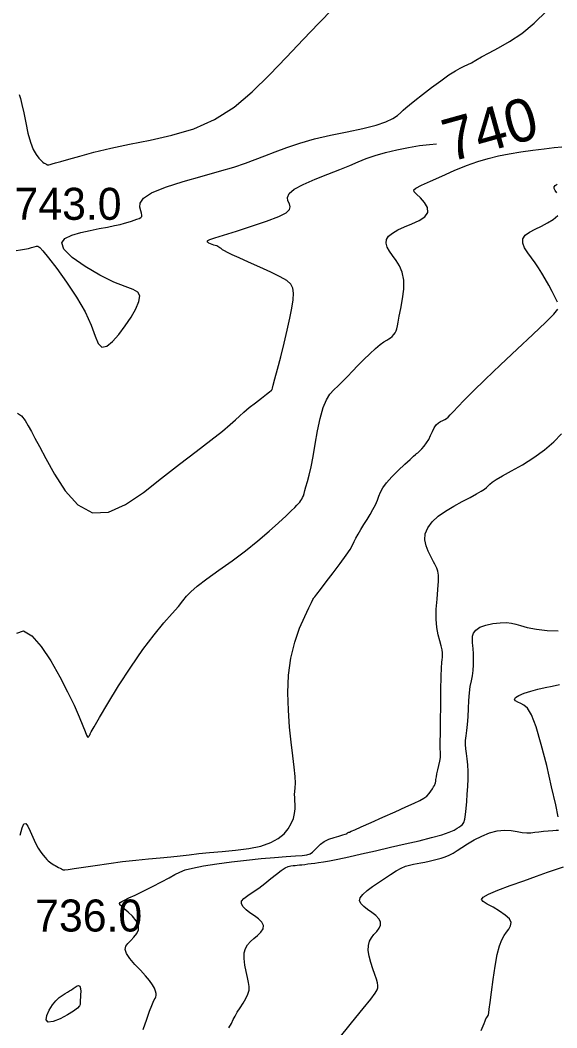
# Model space of a CAD drawing. Extents: x 2566142 to 2571431, y 418755 to 421584.
# Drawn here: x 2570246.2 to 2570497.9, y 419800.8 to 420273.2 of the extents above; entities that cross this region are included whole.
import ezdxf

# ---------------------------------------------------------------- set-up
doc = ezdxf.new("R2010")
doc.units = 0
for name, color, linetype in [('Contour_ADS_Label_Major', 7, 'Continuous'), ('Contour_ADS_Major', 7, 'Continuous'), ('Contour_ADS_Minor', 7, 'Continuous'), ('Contour_ADS_Spot_Elevation', 7, 'Continuous')]:
    doc.layers.add(name, color=color, linetype=linetype)

msp = doc.modelspace()

# ---------------------------------------------------------------- linework, layer by layer
at = {"layer": 'Contour_ADS_Major'}
for points in [[(2570364.23, 420099.94), (2570364.25, 420099.97), (2570364.3, 420100.08), (2570364.47, 420100.66), (2570364.89, 420102.17), (2570365.66, 420105.07), (2570366.87, 420109.65), (2570368.36, 420115.44), (2570369.95, 420121.76), (2570371.45, 420127.94), (2570372.68, 420133.45), (2570373.59, 420138.15), (2570374.15, 420142.06), (2570374.32, 420145.18), (2570374.03, 420147.54), (2570373.06, 420149.43), (2570371.16, 420151.13), (2570368.06, 420152.95), (2570363.66, 420155.12), (2570358.51, 420157.47), (2570353.33, 420159.77), (2570348.83, 420161.75), (2570345.54, 420163.25), (2570343.34, 420164.31), (2570341.94, 420165.06), (2570341.04, 420165.63), (2570340.38, 420166.11), (2570339.86, 420166.53), (2570339.39, 420166.88), (2570338.9, 420167.16), (2570338.33, 420167.38), (2570337.68, 420167.56), (2570336.97, 420167.76), (2570336.21, 420168.01), (2570335.43, 420168.35), (2570334.72, 420168.75), (2570334.19, 420169.17), (2570333.93, 420169.56), (2570334.12, 420169.93), (2570335.15, 420170.41), (2570337.48, 420171.19), (2570341.58, 420172.46), (2570347.63, 420174.33), (2570354.73, 420176.6), (2570361.72, 420178.96), (2570367.41, 420181.15), (2570370.93, 420182.95), (2570372.56, 420184.43), (2570372.86, 420185.76), (2570372.41, 420187.08), (2570371.78, 420188.51), (2570371.56, 420190.13), (2570372.32, 420191.94), (2570374.65, 420193.97), (2570378.89, 420196.24), (2570384.45, 420198.62), (2570390.48, 420200.98), (2570396.13, 420203.17), (2570400.78, 420205.09), (2570404.74, 420206.78), (2570408.51, 420208.3), (2570412.63, 420209.73), (2570417.46, 420211.11), (2570422.79, 420212.4), (2570428.24, 420213.52), (2570433.43, 420214.4), (2570438.11, 420214.99), (2570441.48, 420215.29)], [(2570244.99, 420088.96), (2570246.77, 420087.73), (2570248.44, 420085.56), (2570249.98, 420083), (2570251.45, 420080.39), (2570253.09, 420077.35), (2570255.24, 420073.33), (2570258.21, 420067.74), (2570262.24, 420060.42), (2570267.29, 420052.63), (2570273.28, 420046.03), (2570280.08, 420042.27), (2570287.59, 420042.53), (2570295.61, 420046.11), (2570303.96, 420051.82), (2570312.45, 420058.47), (2570320.83, 420065.03), (2570328.69, 420071.08), (2570335.56, 420076.36), (2570340.99, 420080.61), (2570344.7, 420083.67), (2570347.16, 420085.87), (2570349.05, 420087.65), (2570351.05, 420089.45), (2570353.62, 420091.58), (2570356.53, 420093.89), (2570359.35, 420096.07), (2570361.65, 420097.83), (2570363.12, 420098.95), (2570363.88, 420099.54), (2570364.16, 420099.78), (2570364.2, 420099.84), (2570364.21, 420099.87), (2570364.22, 420099.9), (2570364.23, 420099.94)], [(2570498.54, 419899.8), (2570497.32, 419905.45), (2570495.44, 419913.85), (2570493.11, 419923.8), (2570490.59, 419933.71), (2570488.15, 419942.01), (2570486, 419947.52), (2570484.13, 419950.63), (2570482.46, 419952.15), (2570480.92, 419952.88), (2570479.5, 419953.47), (2570478.42, 419954.12), (2570477.99, 419954.84), (2570478.48, 419955.68), (2570480.09, 419956.67), (2570482.59, 419957.72), (2570485.68, 419958.74), (2570489.01, 419959.65), (2570492.35, 419960.38), (2570495.67, 419961.05), (2570499.04, 419961.8)], [(2570430.59, 419877.53), (2570432.34, 419877.83), (2570434.15, 419878.17), (2570436.01, 419878.57), (2570437.92, 419879), (2570439.84, 419879.44), (2570441.76, 419879.89), (2570443.67, 419880.39), (2570445.55, 419880.99), (2570447.38, 419881.76), (2570449.2, 419882.75), (2570451.12, 419883.96), (2570453.31, 419885.4), (2570455.94, 419887.07), (2570459.1, 419888.92), (2570462.63, 419890.75), (2570466.33, 419892.29), (2570469.96, 419893.28), (2570473.35, 419893.57), (2570476.44, 419893.34), (2570479.22, 419892.87), (2570481.65, 419892.44), (2570483.75, 419892.27), (2570485.65, 419892.32), (2570487.51, 419892.52), (2570489.48, 419892.77), (2570491.66, 419893), (2570493.88, 419893.19), (2570495.93, 419893.35), (2570497.57, 419893.47), (2570498.64, 419893.57)], [(2570395.13, 419795.21), (2570401.61, 419803.19), (2570407.02, 419809.86), (2570410.64, 419814.37), (2570412.69, 419817.07), (2570413.64, 419818.6), (2570413.92, 419819.62), (2570413.92, 419820.7), (2570413.69, 419822.02), (2570413.23, 419823.69), (2570412.53, 419825.83), (2570411.6, 419828.48), (2570410.62, 419831.44), (2570409.81, 419834.43), (2570409.37, 419837.18), (2570409.46, 419839.49), (2570410.03, 419841.41), (2570410.95, 419843.07), (2570412.11, 419844.58), (2570413.37, 419846.06), (2570414.49, 419847.52), (2570415.19, 419848.99), (2570415.22, 419850.47), (2570414.4, 419851.98), (2570412.92, 419853.49), (2570411.06, 419854.96), (2570409.13, 419856.36), (2570407.38, 419857.69), (2570406.06, 419858.99), (2570405.39, 419860.33), (2570405.6, 419861.79), (2570406.81, 419863.41), (2570408.85, 419865.17), (2570411.42, 419867.04), (2570414.26, 419868.98), (2570417.11, 419870.93), (2570419.87, 419872.79), (2570422.47, 419874.42), (2570424.84, 419875.72), (2570426.94, 419876.61), (2570428.82, 419877.16), (2570430.59, 419877.53)]]:
    msp.add_lwpolyline(points, dxfattribs=at)
at = {"layer": 'Contour_ADS_Minor'}
for points in [[(2570245.76, 420238.35), (2570246.34, 420236.47), (2570247.02, 420233.67), (2570247.83, 420229.71), (2570248.75, 420225.04), (2570249.8, 420220.27), (2570250.98, 420215.98), (2570252.28, 420212.66), (2570253.61, 420210.26), (2570254.87, 420208.58), (2570255.96, 420207.46), (2570256.8, 420206.71), (2570257.42, 420206.24), (2570257.87, 420205.97), (2570258.17, 420205.81), (2570258.39, 420205.68), (2570258.55, 420205.58), (2570258.68, 420205.5), (2570258.8, 420205.44), (2570258.94, 420205.4), (2570259.18, 420205.41), (2570259.57, 420205.47), (2570260.18, 420205.61), (2570261.13, 420205.85), (2570262.69, 420206.28), (2570265.18, 420206.98), (2570268.93, 420208.04), (2570274.16, 420209.51), (2570280.78, 420211.27), (2570288.62, 420213.2), (2570297.5, 420215.13), (2570307.21, 420217.03), (2570317.37, 420219.27), (2570327.57, 420222.3), (2570337.38, 420226.6), (2570346.49, 420232.48), (2570355, 420239.64), (2570363.11, 420247.6), (2570371.02, 420255.91), (2570378.82, 420264.11), (2570386.21, 420271.8), (2570392.78, 420278.55)], [(2570425.83, 420230.97), (2570427.09, 420232.07), (2570428.79, 420233.5), (2570431.32, 420235.53), (2570434.88, 420238.34), (2570439.09, 420241.59), (2570443.4, 420244.82), (2570447.27, 420247.56), (2570450.29, 420249.47), (2570452.58, 420250.72), (2570454.43, 420251.59), (2570456.1, 420252.37), (2570457.85, 420253.29), (2570459.95, 420254.48), (2570462.61, 420255.98), (2570466.07, 420257.87), (2570470.5, 420260.22), (2570475.69, 420263.2), (2570481.38, 420267), (2570487.3, 420271.81), (2570493.15, 420277.65)], [(2570244.31, 420165.29), (2570246.31, 420165.54), (2570248.25, 420165.85), (2570250, 420166.22), (2570251.52, 420166.6), (2570252.78, 420166.94), (2570253.76, 420167.2), (2570254.5, 420167.25), (2570255.38, 420166.68), (2570256.87, 420165.02), (2570259.42, 420161.81), (2570263.29, 420156.76), (2570267.95, 420150.37), (2570272.64, 420143.36), (2570276.64, 420136.42), (2570279.4, 420130.21), (2570281.27, 420125.14), (2570282.77, 420121.59), (2570284.46, 420119.93), (2570286.74, 420120.38), (2570289.5, 420122.55), (2570292.49, 420125.9), (2570295.47, 420129.89), (2570298.2, 420134.02), (2570300.41, 420137.96), (2570301.84, 420141.41), (2570302.23, 420144.05), (2570301.35, 420145.75), (2570299.09, 420146.97), (2570295.38, 420148.32), (2570290.16, 420150.44), (2570283.58, 420153.72), (2570276.63, 420157.78), (2570270.56, 420162.02), (2570266.6, 420165.84), (2570265.63, 420168.78), (2570267.19, 420170.91), (2570270.45, 420172.46), (2570274.62, 420173.64), (2570278.97, 420174.63), (2570283.19, 420175.48), (2570287.08, 420176.23), (2570290.43, 420176.89), (2570293.09, 420177.49), (2570295.17, 420178.04), (2570296.86, 420178.55), (2570298.32, 420179.01), (2570299.7, 420179.46), (2570300.95, 420179.89), (2570302, 420180.32), (2570302.77, 420180.75), (2570303.19, 420181.23), (2570303.3, 420181.83), (2570303.14, 420182.68), (2570302.74, 420183.87), (2570302.28, 420185.5), (2570302.43, 420187.5), (2570304.01, 420189.79), (2570307.81, 420192.3), (2570314.31, 420194.93), (2570322.61, 420197.56), (2570331.49, 420200.09), (2570339.73, 420202.38), (2570346.4, 420204.37), (2570351.78, 420206.14), (2570356.44, 420207.84), (2570360.96, 420209.61), (2570365.84, 420211.54), (2570371.27, 420213.57), (2570377.34, 420215.6), (2570384.18, 420217.53), (2570391.76, 420219.28), (2570399.54, 420220.9), (2570406.88, 420222.44), (2570413.1, 420223.98), (2570417.73, 420225.57), (2570420.95, 420227.14), (2570423.13, 420228.6), (2570424.63, 420229.89), (2570425.83, 420230.97)], [(2570426.42, 420176.29), (2570429.89, 420177.76), (2570433.25, 420179.33), (2570435.93, 420181.09), (2570437.36, 420183.09), (2570437.16, 420185.37), (2570435.78, 420187.72), (2570433.86, 420189.89), (2570432.04, 420191.63), (2570430.89, 420192.79), (2570430.73, 420193.64), (2570431.81, 420194.52), (2570434.4, 420195.81), (2570438.59, 420197.76), (2570443.92, 420200.16), (2570449.79, 420202.68), (2570455.57, 420205.02), (2570460.81, 420206.91), (2570465.67, 420208.4), (2570470.47, 420209.58), (2570475.51, 420210.58), (2570480.99, 420211.46), (2570486.61, 420212.24), (2570491.93, 420212.91), (2570496.55, 420213.46), (2570500.14, 420213.9)], [(2570497.9, 420192.28), (2570497.15, 420193.36), (2570496.68, 420194.25), (2570496.62, 420195.02), (2570497.08, 420195.71), (2570498.05, 420196.37)], [(2570498.13, 420141.01), (2570497.07, 420143.25), (2570495.69, 420146), (2570494.12, 420148.98), (2570492.47, 420151.93), (2570490.86, 420154.62), (2570489.25, 420157.11), (2570487.63, 420159.48), (2570485.95, 420161.82), (2570484.23, 420164.2), (2570482.76, 420166.55), (2570481.86, 420168.76), (2570481.86, 420170.74), (2570482.99, 420172.42), (2570485.04, 420173.89), (2570487.69, 420175.25), (2570490.62, 420176.65), (2570493.52, 420178.16), (2570496.15, 420179.81), (2570498.3, 420181.58)], [(2570264.74, 419965.45), (2570268.41, 419958.39), (2570271.43, 419952.05), (2570273.81, 419946.66), (2570275.56, 419942.5), (2570276.69, 419939.72), (2570277.34, 419938.1), (2570277.68, 419937.32), (2570277.86, 419937.07), (2570278.01, 419937.07), (2570278.16, 419937.21), (2570278.31, 419937.44), (2570278.46, 419937.67), (2570278.62, 419937.87), (2570278.75, 419938.03), (2570278.87, 419938.19), (2570278.95, 419938.36), (2570279.05, 419938.66), (2570279.53, 419939.65), (2570280.81, 419941.97), (2570283.3, 419946.26), (2570287.27, 419952.9), (2570292.36, 419961.13), (2570298.01, 419969.89), (2570303.7, 419978.17), (2570308.96, 419985.11), (2570313.59, 419990.69), (2570317.45, 419995.07), (2570320.41, 419998.44), (2570322.47, 420001), (2570324.17, 420003.14), (2570326.19, 420005.3), (2570329.21, 420007.91), (2570333.7, 420011.28), (2570339.33, 420015.32), (2570345.55, 420019.79), (2570351.83, 420024.49), (2570357.69, 420029.19), (2570362.92, 420033.64), (2570367.35, 420037.61), (2570370.85, 420040.85), (2570373.32, 420043.19), (2570374.95, 420044.78), (2570376, 420045.85), (2570376.71, 420046.64), (2570377.31, 420047.34), (2570377.83, 420048.02), (2570378.28, 420048.71), (2570378.66, 420049.45), (2570379, 420050.28), (2570379.33, 420051.31), (2570379.72, 420052.67), (2570380.22, 420054.49), (2570380.88, 420056.89), (2570381.68, 420059.99), (2570382.59, 420063.91), (2570383.56, 420068.75), (2570384.58, 420074.5), (2570385.68, 420080.64), (2570386.89, 420086.55), (2570388.24, 420091.58), (2570389.78, 420095.27), (2570391.48, 420097.9), (2570393.33, 420099.91), (2570395.3, 420101.77), (2570397.4, 420103.83), (2570399.63, 420106.15), (2570402.02, 420108.68), (2570404.61, 420111.37), (2570407.38, 420114.16), (2570410.18, 420116.87), (2570412.8, 420119.28), (2570415.04, 420121.2), (2570416.77, 420122.48), (2570418.07, 420123.28), (2570419.06, 420123.82), (2570419.89, 420124.33), (2570420.67, 420124.99), (2570421.39, 420125.79), (2570422, 420126.69), (2570422.48, 420127.62), (2570422.81, 420128.6), (2570423.1, 420129.86), (2570423.44, 420131.69), (2570423.97, 420134.39), (2570424.74, 420138.12), (2570425.53, 420142.52), (2570426.06, 420147.11), (2570426.06, 420151.41), (2570425.34, 420155.04), (2570424.07, 420158.05), (2570422.48, 420160.6), (2570420.84, 420162.85), (2570419.39, 420164.93), (2570418.3, 420166.88), (2570417.76, 420168.69), (2570417.95, 420170.38), (2570418.99, 420171.94), (2570420.82, 420173.43), (2570423.33, 420174.86), (2570426.42, 420176.29)], [(2570407.38, 420036.73), (2570408.85, 420039.14), (2570410.28, 420041.54), (2570411.62, 420043.88), (2570412.8, 420046.09), (2570413.74, 420048.14), (2570414.44, 420050.03), (2570415.15, 420051.9), (2570416.21, 420053.93), (2570417.92, 420056.32), (2570420.48, 420059.16), (2570423.51, 420062.17), (2570426.54, 420065.01), (2570429.07, 420067.31), (2570430.72, 420068.81), (2570431.64, 420069.64), (2570432.06, 420070.01), (2570432.25, 420070.15), (2570432.43, 420070.27), (2570432.7, 420070.46), (2570433.11, 420070.82), (2570433.72, 420071.43), (2570434.59, 420072.35), (2570435.62, 420073.57), (2570436.71, 420075.04), (2570437.76, 420076.72), (2570438.69, 420078.55), (2570439.54, 420080.4), (2570440.38, 420082.1), (2570441.28, 420083.5), (2570442.31, 420084.48), (2570443.38, 420085.13), (2570444.42, 420085.59), (2570445.35, 420085.98), (2570446.12, 420086.45), (2570446.9, 420087.15), (2570447.9, 420088.2), (2570449.34, 420089.78), (2570451.44, 420092.02), (2570454.46, 420095.14), (2570458.65, 420099.33), (2570464.29, 420104.81), (2570471.41, 420111.59), (2570479.21, 420118.93), (2570486.63, 420125.92), (2570492.63, 420131.63), (2570496.44, 420135.42), (2570498.28, 420137.75)], [(2570436.83, 419909.52), (2570437.92, 419910.66), (2570438.81, 419911.84), (2570439.51, 419912.94), (2570440.04, 419913.85), (2570440.42, 419914.48), (2570440.68, 419914.92), (2570440.86, 419915.3), (2570440.98, 419915.76), (2570441.08, 419916.41), (2570441.19, 419917.3), (2570441.37, 419918.48), (2570441.65, 419919.99), (2570442.05, 419921.82), (2570442.51, 419923.82), (2570442.93, 419925.79), (2570443.23, 419927.52), (2570443.35, 419928.87), (2570443.34, 419929.86), (2570443.25, 419930.59), (2570443.17, 419931.13), (2570443.13, 419931.64), (2570443.15, 419932.68), (2570443.2, 419934.85), (2570443.26, 419938.78), (2570443.32, 419944.8), (2570443.4, 419952.03), (2570443.49, 419959.32), (2570443.62, 419965.49), (2570443.78, 419969.67), (2570443.95, 419972.17), (2570444.11, 419973.59), (2570444.24, 419974.51), (2570444.29, 419975.45), (2570444.24, 419976.6), (2570444.01, 419978.05), (2570443.58, 419979.89), (2570442.92, 419982.21), (2570442.18, 419985.06), (2570441.55, 419988.48), (2570441.23, 419992.5), (2570441.32, 419997.08), (2570441.69, 420001.86), (2570442.13, 420006.39), (2570442.41, 420010.22), (2570442.39, 420013.04), (2570442.11, 420014.99), (2570441.66, 420016.33), (2570441.15, 420017.34), (2570440.65, 420018.25), (2570440.1, 420019.26), (2570439.44, 420020.5), (2570438.58, 420022.15), (2570437.53, 420024.3), (2570436.56, 420026.85), (2570435.98, 420029.63), (2570436.15, 420032.5), (2570437.31, 420035.31), (2570439.39, 420038.03), (2570442.24, 420040.64), (2570445.69, 420043.12), (2570449.55, 420045.46), (2570453.5, 420047.6), (2570457.18, 420049.5), (2570460.25, 420051.1), (2570462.43, 420052.37), (2570463.88, 420053.38), (2570464.85, 420054.21), (2570465.59, 420054.95), (2570466.38, 420055.69), (2570467.54, 420056.59), (2570469.43, 420057.82), (2570472.39, 420059.55), (2570476.64, 420061.9), (2570481.73, 420064.81), (2570487.1, 420068.15), (2570492.16, 420071.79), (2570496.46, 420075.58), (2570499.98, 420079.29)], [(2570246.13, 419891.1), (2570247.04, 419894.61), (2570247.87, 419896.44), (2570248.75, 419896.64), (2570249.76, 419895.36), (2570250.9, 419893.04), (2570252.11, 419890.22), (2570253.37, 419887.43), (2570254.62, 419885.09), (2570255.81, 419883.24), (2570256.91, 419881.79), (2570257.86, 419880.67), (2570258.64, 419879.82), (2570259.28, 419879.16), (2570259.87, 419878.63), (2570260.48, 419878.18), (2570261.15, 419877.74), (2570261.88, 419877.31), (2570262.65, 419876.89), (2570263.42, 419876.48), (2570264.17, 419876.08), (2570264.86, 419875.71), (2570265.48, 419875.39), (2570265.98, 419875.13), (2570266.41, 419874.96), (2570267.17, 419874.93), (2570268.72, 419875.09), (2570271.51, 419875.49), (2570275.85, 419876.15), (2570281.41, 419876.99), (2570287.68, 419877.9), (2570294.17, 419878.76), (2570300.45, 419879.47), (2570306.37, 419880.06), (2570311.84, 419880.57), (2570316.8, 419881.05), (2570321.23, 419881.54), (2570325.46, 419882.03), (2570329.9, 419882.52), (2570334.94, 419883), (2570340.84, 419883.5), (2570347.19, 419884.1), (2570353.46, 419884.92), (2570359.1, 419886.08), (2570363.67, 419887.66), (2570367.22, 419889.61), (2570369.91, 419891.81), (2570371.9, 419894.18), (2570373.33, 419896.61), (2570374.31, 419899.04), (2570374.89, 419901.37), (2570375.15, 419903.54), (2570375.17, 419905.49), (2570375.06, 419907.24), (2570374.93, 419908.82), (2570374.88, 419910.28), (2570374.99, 419911.7), (2570375.16, 419913.37), (2570375.26, 419915.61), (2570375.13, 419918.74), (2570374.7, 419923.01), (2570374.04, 419928.38), (2570373.27, 419934.71), (2570372.54, 419941.87), (2570371.98, 419949.71), (2570371.77, 419957.93), (2570372.08, 419966.2), (2570373.12, 419974.2), (2570374.95, 419981.62), (2570377.25, 419988.19), (2570379.6, 419993.65), (2570381.56, 419997.73), (2570382.82, 420000.28), (2570383.48, 420001.62), (2570383.74, 420002.14), (2570383.81, 420002.26), (2570383.92, 420002.39), (2570384.3, 420002.88), (2570385.24, 420004.08), (2570387, 420006.35), (2570389.72, 420009.86), (2570392.99, 420014.13), (2570396.28, 420018.51), (2570399.05, 420022.35), (2570400.92, 420025.15), (2570402.09, 420027.16), (2570402.89, 420028.76), (2570403.67, 420030.34), (2570404.7, 420032.22), (2570405.97, 420034.39), (2570407.38, 420036.73)], [(2570244.59, 419985.79), (2570247.72, 419986.94), (2570251.62, 419984.63), (2570256.01, 419979.57), (2570260.51, 419972.82), (2570264.74, 419965.45)], [(2570378.31, 419877.33), (2570379.61, 419877.48), (2570381.04, 419877.67), (2570382.62, 419877.87), (2570384.31, 419878.08), (2570386.15, 419878.31), (2570388.39, 419878.62), (2570391.31, 419879.12), (2570395.2, 419879.89), (2570400.25, 419880.99), (2570406.25, 419882.35), (2570412.87, 419883.88), (2570419.8, 419885.48), (2570426.73, 419887.06), (2570433.3, 419888.59), (2570439.14, 419890.02), (2570443.91, 419891.35), (2570447.36, 419892.52), (2570449.68, 419893.55), (2570451.2, 419894.41), (2570452.23, 419895.09), (2570453.04, 419895.63), (2570453.7, 419896.24), (2570454.24, 419897.15), (2570454.68, 419898.62), (2570455.05, 419900.81), (2570455.37, 419903.62), (2570455.65, 419906.88), (2570455.89, 419910.4), (2570456.11, 419914.03), (2570456.25, 419917.63), (2570456.29, 419921.06), (2570456.17, 419924.2), (2570455.88, 419926.95), (2570455.51, 419929.38), (2570455.18, 419931.57), (2570455.01, 419933.61), (2570455.09, 419935.61), (2570455.35, 419937.74), (2570455.69, 419940.18), (2570456.01, 419943.11), (2570456.23, 419946.63), (2570456.4, 419950.5), (2570456.59, 419954.37), (2570456.87, 419957.92), (2570457.28, 419960.91), (2570457.77, 419963.48), (2570458.24, 419965.87), (2570458.6, 419968.33), (2570458.8, 419971.03), (2570458.85, 419973.79), (2570458.79, 419976.37), (2570458.66, 419978.53), (2570458.51, 419980.11), (2570458.37, 419981.26), (2570458.27, 419982.23), (2570458.26, 419983.25), (2570458.39, 419984.51), (2570458.86, 419985.91), (2570459.92, 419987.33), (2570461.78, 419988.61), (2570464.55, 419989.63), (2570467.89, 419990.36), (2570471.29, 419990.78), (2570474.29, 419990.86), (2570476.58, 419990.62), (2570478.56, 419990.09), (2570480.82, 419989.38), (2570483.94, 419988.54), (2570488.31, 419987.7), (2570493.41, 419987.08), (2570498.56, 419986.93)], [(2570303.81, 419800.14), (2570305.51, 419804.87), (2570306.86, 419808.66), (2570307.85, 419811.27), (2570308.56, 419812.92), (2570309.05, 419813.93), (2570309.42, 419814.64), (2570309.72, 419815.32), (2570309.91, 419816.08), (2570309.92, 419816.98), (2570309.7, 419818.08), (2570309.16, 419819.43), (2570308.25, 419821.06), (2570306.88, 419823), (2570304.97, 419825.28), (2570302.54, 419827.88), (2570299.93, 419830.62), (2570297.59, 419833.28), (2570295.96, 419835.64), (2570295.37, 419837.53), (2570295.68, 419839.08), (2570296.65, 419840.45), (2570298.01, 419841.82), (2570299.52, 419843.34), (2570300.84, 419845.02), (2570301.67, 419846.87), (2570301.66, 419848.88), (2570300.62, 419851.02), (2570298.87, 419853.15), (2570296.85, 419855.09), (2570295, 419856.69), (2570293.7, 419857.82), (2570292.97, 419858.58), (2570292.77, 419859.12), (2570293.05, 419859.57), (2570293.79, 419860.07), (2570295.11, 419860.76), (2570297.16, 419861.73), (2570300.07, 419863.12), (2570303.89, 419864.98), (2570308.18, 419867.11), (2570312.41, 419869.26), (2570316.04, 419871.19), (2570318.72, 419872.7), (2570320.98, 419873.87), (2570323.52, 419874.85), (2570327.05, 419875.77), (2570332.09, 419876.75), (2570338.34, 419877.74), (2570345.27, 419878.69), (2570352.37, 419879.53), (2570359.19, 419880.19), (2570365.43, 419880.71), (2570370.86, 419881.11), (2570375.24, 419881.42), (2570378.42, 419881.69), (2570380.62, 419882.01), (2570382.15, 419882.49), (2570383.32, 419883.24), (2570384.39, 419884.32), (2570385.56, 419885.62), (2570386.95, 419886.98), (2570388.73, 419888.25), (2570390.95, 419889.3), (2570393.36, 419890.13), (2570395.65, 419890.77), (2570397.5, 419891.25), (2570398.66, 419891.58), (2570399.25, 419891.81), (2570399.49, 419891.97), (2570399.57, 419892.09), (2570399.68, 419892.2), (2570399.84, 419892.31), (2570400.04, 419892.41), (2570400.27, 419892.52), (2570400.61, 419892.65), (2570401.42, 419892.98), (2570403.12, 419893.71), (2570406.14, 419895.04), (2570410.72, 419897.07), (2570416.27, 419899.55), (2570421.98, 419902.11), (2570427.06, 419904.39), (2570430.89, 419906.12), (2570433.59, 419907.43), (2570435.47, 419908.49), (2570436.83, 419909.52)], [(2570344.08, 419800.84), (2570345.23, 419802.91), (2570346.14, 419804.69), (2570346.99, 419806.37), (2570348, 419808.16), (2570349.28, 419810.19), (2570350.69, 419812.38), (2570352.01, 419814.58), (2570353, 419816.64), (2570353.5, 419818.48), (2570353.55, 419820.25), (2570353.28, 419822.17), (2570352.77, 419824.44), (2570352.16, 419827.21), (2570351.6, 419830.26), (2570351.25, 419833.28), (2570351.28, 419835.98), (2570351.82, 419838.12), (2570352.81, 419839.83), (2570354.16, 419841.29), (2570355.75, 419842.67), (2570357.47, 419844.14), (2570359.01, 419845.69), (2570360.07, 419847.28), (2570360.31, 419848.87), (2570359.54, 419850.43), (2570357.99, 419851.94), (2570356.01, 419853.41), (2570353.93, 419854.84), (2570352.09, 419856.22), (2570350.7, 419857.58), (2570349.96, 419858.91), (2570350.05, 419860.22), (2570351.11, 419861.55), (2570352.96, 419862.96), (2570355.37, 419864.55), (2570358.11, 419866.4), (2570360.96, 419868.56), (2570363.77, 419870.81), (2570366.37, 419872.93), (2570368.65, 419874.65), (2570370.48, 419875.8), (2570371.93, 419876.46), (2570373.13, 419876.78), (2570374.16, 419876.93), (2570375.14, 419877.03), (2570376.13, 419877.11), (2570377.17, 419877.21), (2570378.31, 419877.33)], [(2570462.44, 419799.58), (2570463.73, 419802.84), (2570464.23, 419804.19), (2570464.4, 419804.67), (2570464.64, 419805.12), (2570464.97, 419805.65), (2570465.31, 419806.19), (2570465.6, 419806.66), (2570465.79, 419807.07), (2570465.94, 419807.87), (2570466.17, 419809.58), (2570466.55, 419812.73), (2570467.17, 419817.62), (2570467.98, 419823.59), (2570468.92, 419829.74), (2570469.94, 419835.19), (2570470.99, 419839.24), (2570472.05, 419842.09), (2570473.15, 419844.1), (2570474.27, 419845.68), (2570475.38, 419847.16), (2570476.2, 419848.65), (2570476.38, 419850.2), (2570475.59, 419851.89), (2570473.64, 419853.72), (2570470.92, 419855.6), (2570467.94, 419857.36), (2570465.25, 419858.87), (2570463.34, 419860.05), (2570462.57, 419861.06), (2570463.27, 419862.15), (2570465.77, 419863.54), (2570470.22, 419865.39), (2570476, 419867.56), (2570482.32, 419869.83), (2570488.38, 419871.95), (2570493.52, 419873.76), (2570497.69, 419875.22), (2570500.97, 419876.37)]]:
    msp.add_lwpolyline(points, dxfattribs=at)
msp.add_lwpolyline([(2570271.25, 419808.73), (2570268.33, 419806.92), (2570264.86, 419805.11), (2570261.59, 419803.81), (2570259.22, 419803.54), (2570258.3, 419804.61), (2570258.61, 419806.68), (2570259.73, 419809.2), (2570261.28, 419811.64), (2570262.89, 419813.58), (2570264.45, 419815.01), (2570265.91, 419816.07), (2570267.21, 419816.88), (2570268.32, 419817.55), (2570269.29, 419818.15), (2570270.17, 419818.72), (2570271.05, 419819.33), (2570271.96, 419819.97), (2570272.84, 419820.49), (2570273.6, 419820.68), (2570274.17, 419820.35), (2570274.47, 419819.37), (2570274.56, 419817.96), (2570274.51, 419816.41), (2570274.41, 419815.02), (2570274.33, 419814.01), (2570274.27, 419813.32), (2570274.24, 419812.82), (2570274.25, 419812.38), (2570274.25, 419811.85), (2570273.97, 419811.14), (2570273.08, 419810.13), (2570271.25, 419808.73)], close=True, dxfattribs=at)

# ---------------------------------------------------------------- texts
at = {"layer": 'Contour_ADS_Label_Major'}
msp.add_text('740', height=20, rotation=15.5156, dxfattribs=at).set_placement((2570447.63, 420206.62))
at = {"layer": 'Contour_ADS_Spot_Elevation'}
for s, p in [('743.0', (2570243.52, 420179.63)), ('736.0', (2570253.21, 419846))]:
    msp.add_text(s, height=15, dxfattribs=at).set_placement(p)

doc.saveas('drawing.dxf')
